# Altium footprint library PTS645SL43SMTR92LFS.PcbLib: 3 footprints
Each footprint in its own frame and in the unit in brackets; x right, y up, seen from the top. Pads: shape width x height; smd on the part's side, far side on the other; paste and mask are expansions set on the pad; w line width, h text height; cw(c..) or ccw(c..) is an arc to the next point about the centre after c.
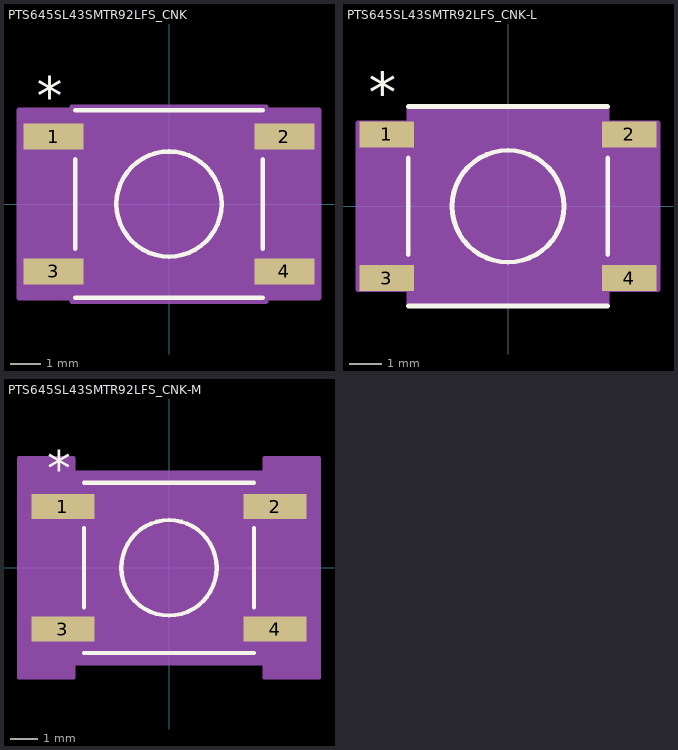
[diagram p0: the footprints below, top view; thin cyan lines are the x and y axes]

## PTS645SL43SMTR92LFS_CNK [mil]
pads (4):
  rect 79x34 smd paste+0 mask+0: 1(-151.5,88.58) 2(151.5,88.58) 3(-151.5,-88.58) 4(151.5,-88.58)
Top Overlay:
  circle w6: c0,0 r69
  lines w6: -123,-123 123,-123 ; -123,-58.48 -123,58.48 ; -123,123 123,123 ; 123,-58.48 123,58.48
  text "*" at -174,117.58 h50
Mechanical 13:
  circle w0: c0,0 r69
  lines w1: -177,-104.58 -177,-72.58 -118,-72.58 -118,-104.58 -177,-104.58 ; -177,72.58 -177,104.58 -118,104.58 -118,72.58 -177,72.58 ; -118,-118 118,-118 118,118 -118,118 -118,-118 ; 118,-104.58 118,-72.58 177,-72.58 177,-104.58 118,-104.58 ; 118,72.58 118,104.58 177,104.58 177,72.58 118,72.58
  text "*" at -115.5,57.58 h50
Mechanical 15:
  region: 128,-128 -128,-128 -128,-123.58 -197,-123.58 -197,123.58 -128,123.58 -128,128 128,128 128,123.58 197,123.58 197,-123.58 128,-123.58
  lines w6: -197,-123.58 -128,-123.58 -128,-128 128,-128 128,-123.58 197,-123.58 197,123.58 128,123.58 128,128 -128,128 -128,123.58 -197,123.58 -197,-123.58

## PTS645SL43SMTR92LFS_CNK-L [mil]
pads (4):
  rect 67x32 smd paste+0 mask+0: 1(-149.5,88.58) 2(149.5,88.58) 3(-149.5,-88.58) 4(149.5,-88.58)
Top Overlay:
  circle w6: c0,0 r69
  lines w6: -123,-123 123,-123 ; -123,-59.48 -123,59.48 ; -123,123 123,123 ; 123,-59.48 123,59.48
  text "*" at -172,115.58 h50
Mechanical 13:
  circle w0: c0,0 r69
  lines w1: -177,-104.58 -177,-72.58 -118,-72.58 -118,-104.58 -177,-104.58 ; -177,72.58 -177,104.58 -118,104.58 -118,72.58 -177,72.58 ; -118,-118 118,-118 118,118 -118,118 -118,-118 ; 118,-104.58 118,-72.58 177,-72.58 177,-104.58 118,-104.58 ; 118,72.58 118,104.58 177,104.58 177,72.58 118,72.58
  text "*" at -115.5,55.58 h50
Mechanical 15:
  region: 122,-122 -122,-122 -122,-102.58 -185,-102.58 -185,102.58 -122,102.58 -122,122 122,122 122,102.58 185,102.58 185,-102.58 122,-102.58
  lines w6: -185,-102.58 -122,-102.58 -122,-122 122,-122 122,-102.58 185,-102.58 185,102.58 122,102.58 122,122 -122,122 -122,102.58 -185,102.58 -185,-102.58

## PTS645SL43SMTR92LFS_CNK-M [mil]
pads (4):
  rect 91x36 smd paste+0 mask+0: 1(-153.5,88.58) 2(153.5,88.58) 3(-153.5,-88.58) 4(153.5,-88.58)
Top Overlay:
  circle w6: c0,0 r69
  lines w6: -123,-123 123,-123 ; -123,-57.48 -123,57.48 ; -123,123 123,123 ; 123,-57.48 123,57.48
  text "*" at -176,119.58 h50
Mechanical 13:
  circle w0: c0,0 r69
  lines w1: -177,-104.58 -177,-72.58 -118,-72.58 -118,-104.58 -177,-104.58 ; -177,72.58 -177,104.58 -118,104.58 -118,72.58 -177,72.58 ; -118,-118 118,-118 118,118 -118,118 -118,-118 ; 118,-104.58 118,-72.58 177,-72.58 177,-104.58 118,-104.58 ; 118,72.58 118,104.58 177,104.58 177,72.58 118,72.58
  text "*" at -115.5,59.58 h50
Mechanical 15:
  region: 138,-138 -138,-138 -138,-158.58 -217,-158.58 -217,158.58 -138,158.58 -138,138 138,138 138,158.58 217,158.58 217,-158.58 138,-158.58
  lines w6: -217,-158.58 -138,-158.58 -138,-138 138,-138 138,-158.58 217,-158.58 217,158.58 138,158.58 138,138 -138,138 -138,158.58 -217,158.58 -217,-158.58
